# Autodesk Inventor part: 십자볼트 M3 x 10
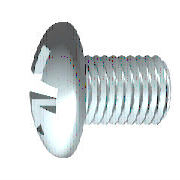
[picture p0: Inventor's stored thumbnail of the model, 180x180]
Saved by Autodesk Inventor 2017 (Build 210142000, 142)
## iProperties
IsCustomPart: 0
Created: 2012-02
Part Number: 십자볼트 M3 x 10
Material: 스테인리스강
Description: 십자 오목 머리 나사
Document SubType Name: Modeling
Standard: KS B 1023
Designer: mduedu
Standards Organization: KS
Language: ko-KR
Size Designation: A  M 3 x 10 - H
Categories: <MemberInstance><Categories><Category DisplayName="조임쇠" InternalName="e4da775c-781d-43d5-af7c-5136215cf5a6" Mnemonic="FSTN"><Category DisplayName="볼트" InternalN
Density: 1 g/cm^3
Appearance: 반광택
Author: mduedu
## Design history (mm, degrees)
workplane "Work Plane3"
sketch "스케치2"
  geometry: L1 (-3.72, 0)-(3.72, 0) reference; L2 (0, -3.72)-(0, 3.72) reference; L3 (0, 1.5)-(0, 0); L4 (0, 0)-(1.5, 0); L5 (0, 0)-(1.879, 1.879); L6 (0.253, 1.479)-(0.261, 0.456); L7 (1.479, 0.253)-(0.456, 0.261); L8 (0.253, -1.479)-(0.261, -0.456); L9 (1.479, -0.253)-(0.456, -0.261); L10 (-0.253, 1.479)-(-0.261, 0.456); L11 (-1.479, 0.253)-(-0.456, 0.261); L12 (-1.479, -0.253)-(-0.456, -0.261); L13 (-0.253, -1.479)-(-0.261, -0.456); A1 r 0.45 centre (0, 0) between (0.45, 0) and (0, 0.45); A2 r 1.5 centre (0, 0) between (1.5, 0) and (1.479, 0.253); A3 r 1.5 centre (0, 0) between (0.253, 1.479) and (0, 1.5); A4 r 1.5 centre (0, 0) between (1.479, 0.253) and (0.253, 1.479); A5 r 1.5 centre (0, 0) between (0, -1.5) and (0.253, -1.479); A6 r 1.5 centre (0, 0) between (0.253, -1.479) and (1.479, -0.253); A7 r 1.5 centre (0, 0) between (1.479, -0.253) and (1.5, 0); A8 r 1.5 centre (0, 0) between (-1.479, 0.253) and (-1.5, 0); A9 r 1.5 centre (0, 0) between (-0.253, 1.479) and (-1.479, 0.253); A10 r 1.5 centre (0, 0) between (0, 1.5) and (-0.253, 1.479); A11 r 1.5 centre (0, 0) between (-1.5, 0) and (-1.479, -0.253); A12 r 1.5 centre (0, 0) between (-1.479, -0.253) and (-0.253, -1.479); A13 r 1.5 centre (0, 0) between (-0.253, -1.479) and (0, -1.5); A14 r 0.525 centre (0, 0) between (0.525, 0) and (0, 0.525); A15 r 0.197 centre (0.457, 0.457) between (0.261, 0.456) and (0.456, 0.261); A16 r 0.197 centre (0.457, -0.457) between (0.456, -0.261) and (0.261, -0.456); A17 r 0.197 centre (-0.457, 0.457) between (-0.456, 0.261) and (-0.261, 0.456); A18 r 0.197 centre (-0.457, -0.457) between (-0.261, -0.456) and (-0.456, -0.261); 1 further point
  constraints: 38 point on circle, 22 end point, 19 symmetric about line, 18 centre point, 4 coincident, 3 collinear, 3 point on line, 3 tangent, 1 perpendicular, 21 other
  dimensions: "d4" = 45 deg angle of L5 L4; "d5" = 0.9 diameter of A1 (= 0.3 x SDM); "d6" = 3 diameter of A4 (= SDM); "d7" = 0.2525 distance from line of L6.start L3 (= 0.5 x SBR); "d14" = 1.05 diameter of A14 (= 0.35 x SDM)
extrude "슬롯" join sketch "스케치2" taper "d15" = 5 deg; stored distance "d54" = 10
revolve "절단부" stored, may be unused: angle "d56" = 90 deg
revolve "본체" stored, may be unused: angle "d18" = 90 deg
workplane "Work Plane1"
body "Solid1"
sketch "스케치1"
  geometry: L1 (10, 0)-(10, 1.5); L2 (10, 1.5)-(1, 1.5); L3 (3.962, 5.08)-(3.962, 5.08); L4 (-2.4, 0)-(-2.4, 2.59); L5 (-2.2, 1.4)-(-1.036, 0.82); L6 (-1.036, 0.82)-(-0.6, 0); L7 (-0.6, 0)-(10, 0); L8 (-5.105, 0)-(12.517, 0) reference; L9 (0, -1.016)-(0, 6.096) reference; L10 (-2.2, 1.4)-(-2.4, 1.5); L11 (-1.636, 2.657)-(-2.4, 2.59); L12 (-1.636, 2.657)-(0, 2.8); L13 (0, 2.8)-(0, 1.347); L14 (0, 1.347)-(0.693, 1.347); L15 (0.693, 1.347)-(1, 1.5); L16 (1, 1.5)-(0, 1.5); A1 r 5 centre (2.6, 0) between (-1.636, 2.657) and (-2.4, 0)
  constraints: 28 end point, 5 point on line, 4 collinear, 4 point on circle, 3 parallel, 2 perpendicular, 1 centre point, 1 horizontal, 1 tangent
  dimensions: "d1" = 3 diameter of L2 L7 (= GD); "d2" = 1.8 distance from line of L6.end L4 (= STI); "d11" = 3 diameter of L10.end L7 (= SDM); "d12" = 62 deg angle of L6 L7; "d13" = 26.5 deg angle of L5 L7; "d17" = 5.6 diameter of L12.end L7 (= KOD); "d19" = 5 deg angle of L12 L7 (= KEWI); "d20" = 2.4 distance between parallel lines of L4 L13 (= KOH); "d21" = 5 radius of A1 (= KR); "d23" = 2.6935 diameter of L14 L7 (= BDM); "d24" = 9 distance of L1.end L2.end (= GEL); "d25" = 0.30673 horizontal distance of L14.end L2.end (= GAL); "d28" = 10 distance between parallel lines of L1 L13 (= NLG)
fillet "모깎기1" dims "d29" = 1.2 (= RR)
fillet "모깎기2" dims "d16" = 0.101 (= 0.2 x SBR)
feature "스레드" dims "d8" = 9 (= GEL), "d9" = 0
chamfer "모따기1" distance "d26" = 0.30673 (= -0.5 x SPD + 0.5 x GD); stored, may be unused: second distance "d27" = 0.30683 (computed from GUL), angle "d78" = 45 deg
other parameters: "GD" = 3 (= NND) [user parameter; used in 2 equation terms], "NLG" = 10 [user parameter; used in 1 equation term], "GEL" = 9 [user parameter; used in 2 equation terms], "KOD" = 5.6 [user parameter; used in 1 equation term], "KOH" = 2.4 [user parameter; used in 2 equation terms], "SDM" = 3 [user parameter; used in 4 equation terms], "STI" = 1.8 [user parameter; used in 1 equation term], "SBR" = 0.505 [user parameter; used in 2 equation terms], "GAL" = 0.30673 (= 0.61345 x PTC) [user parameter; used in 1 equation term], "SPD" = 2.38655 (= NND - 1.2269 x PTC) [user parameter; used in 1 equation term], "KEWI" = 5 deg [user parameter; used in 1 equation term], "d3" = -2.4 (= -KOH), "d10" = 0, "KR" = 5 [user parameter; used in 1 equation term], "BDM" = 2.6935 [user parameter; used in 1 equation term], "GUL" = 0.30673 (= 0.61345 x PTC) [user parameter; used in 1 equation term], "RR" = 1.2 [user parameter; used in 1 equation term], "d79" = 0, "d80" = 0, "PTC" = 0.5 [user parameter; used in 5 equation terms], "THREADDIA" = 3 [user parameter; used in 1 equation term], "TOA" = 30 deg [user parameter], "NND" = 3 [user parameter; used in 2 equation terms], "GD1" = 2.38655 (= THREADDIA - 1.2269 x PTC) [user parameter]
